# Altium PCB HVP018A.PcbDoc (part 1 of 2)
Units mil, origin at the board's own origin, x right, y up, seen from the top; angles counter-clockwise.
Board outline 2060 x 1591 mil, 4 copper layers (Top Layer, MidLayer1, MidLayer2, Bottom Layer), stack 46.2 mil thick; 91 components, 51 nets, 302 pads, 340 vias.
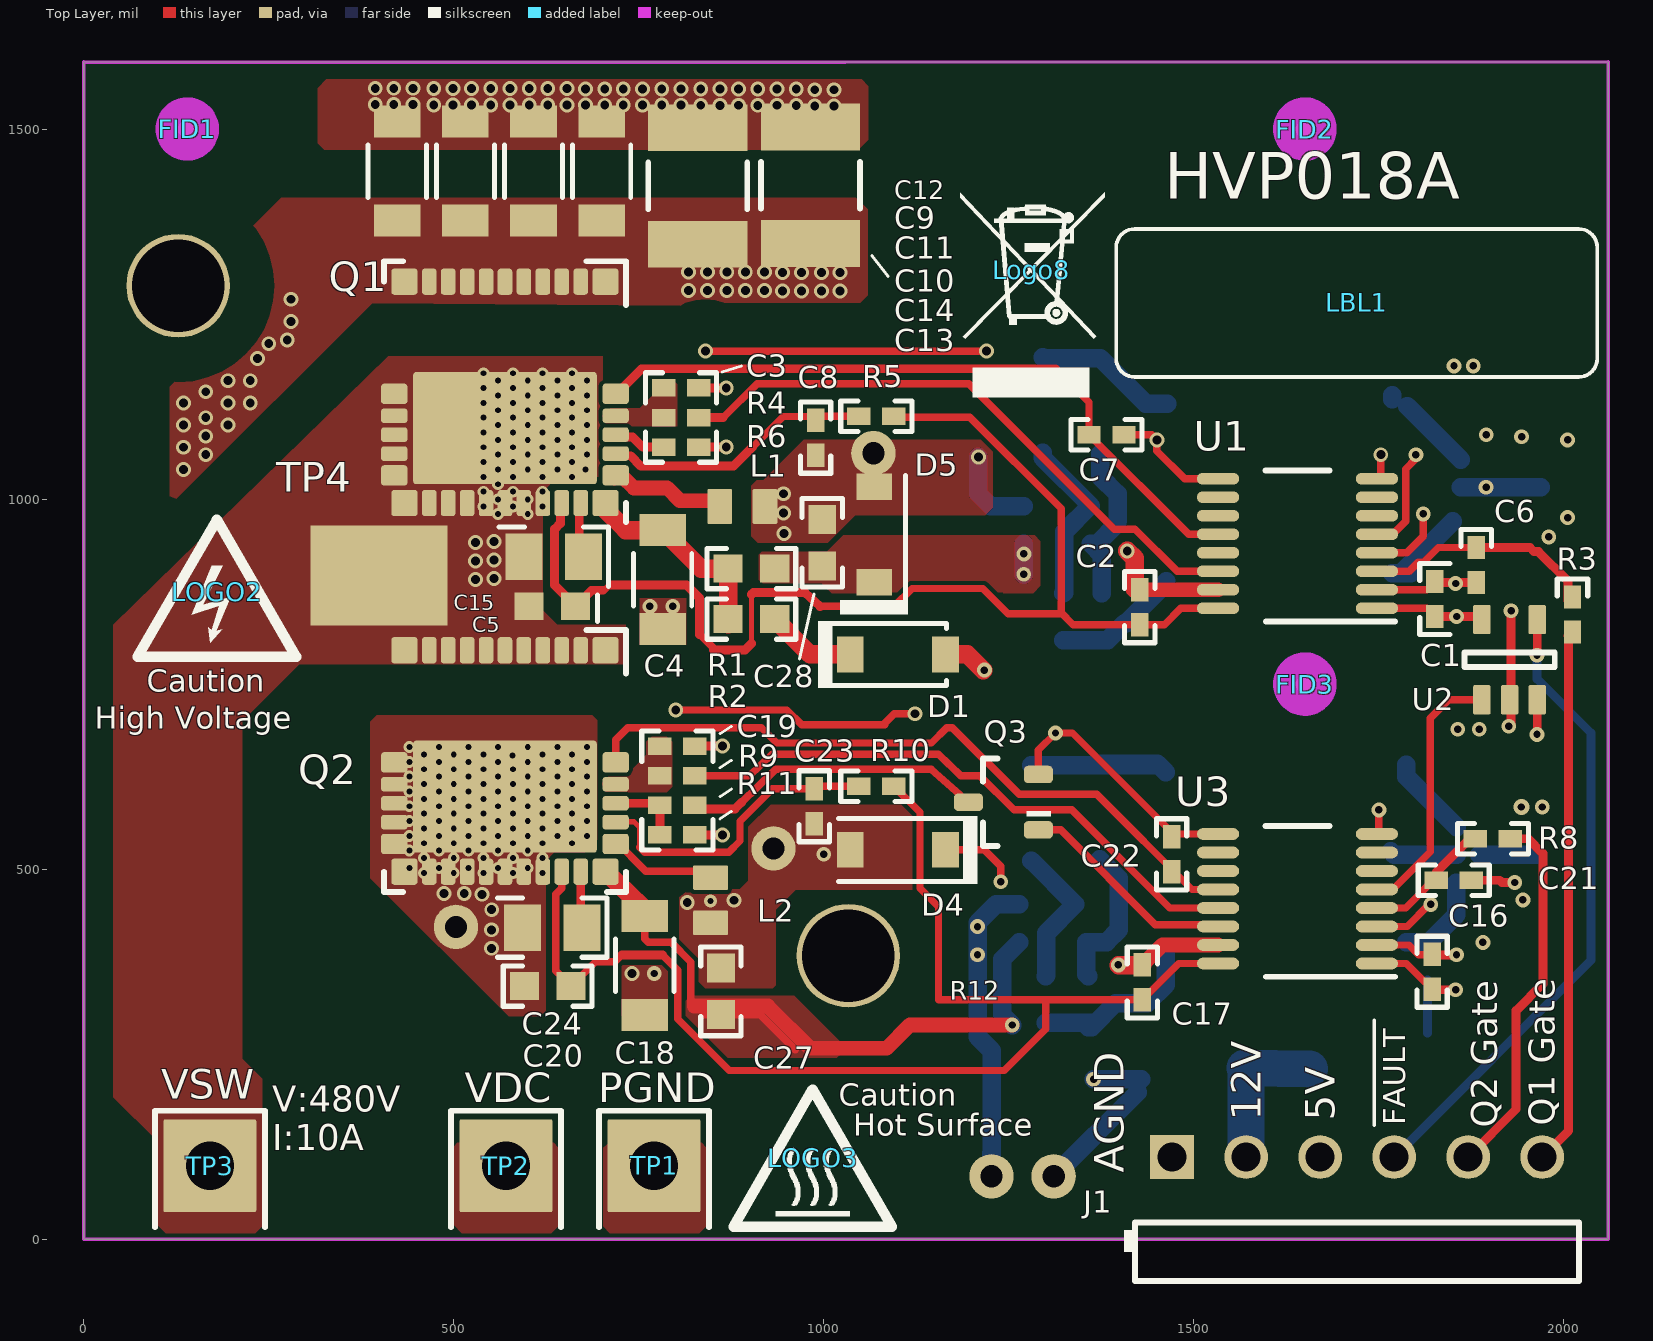
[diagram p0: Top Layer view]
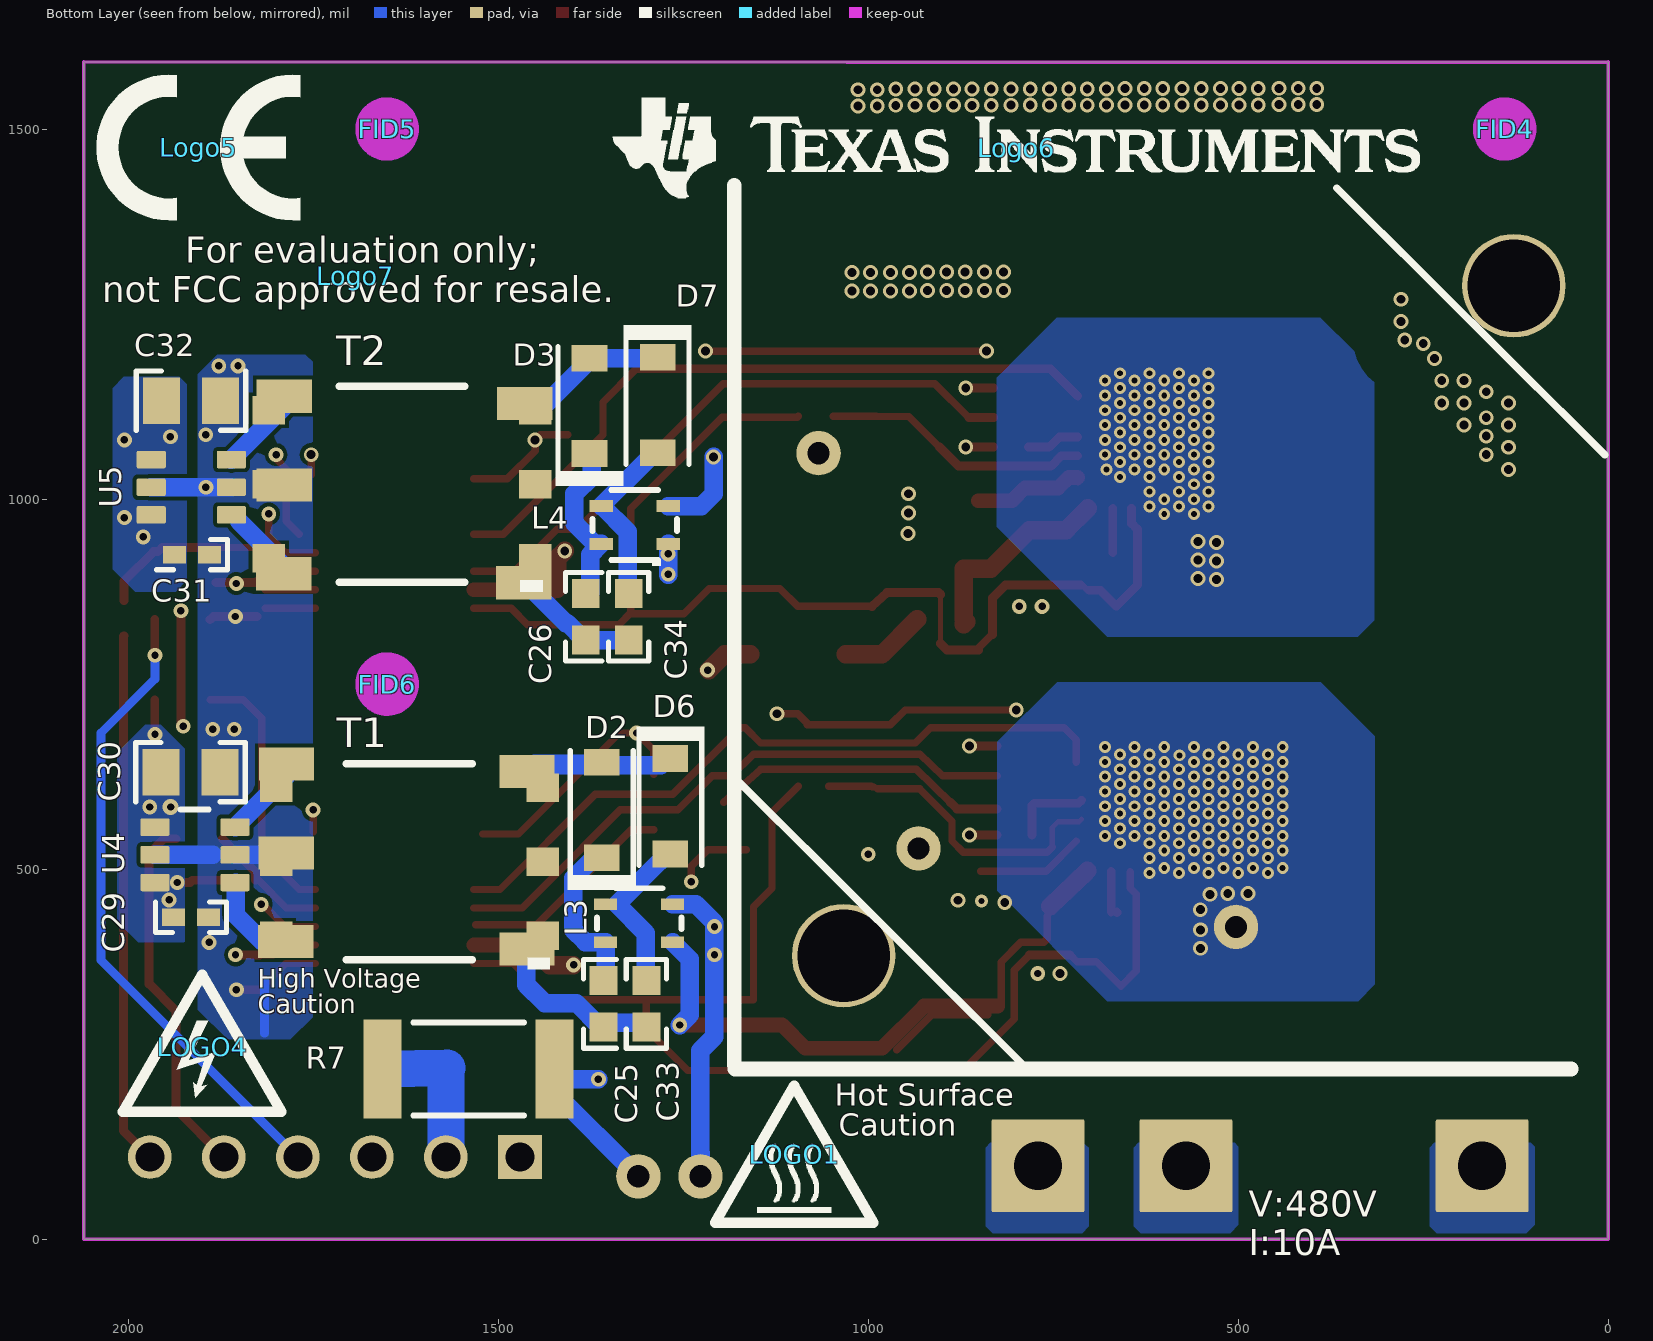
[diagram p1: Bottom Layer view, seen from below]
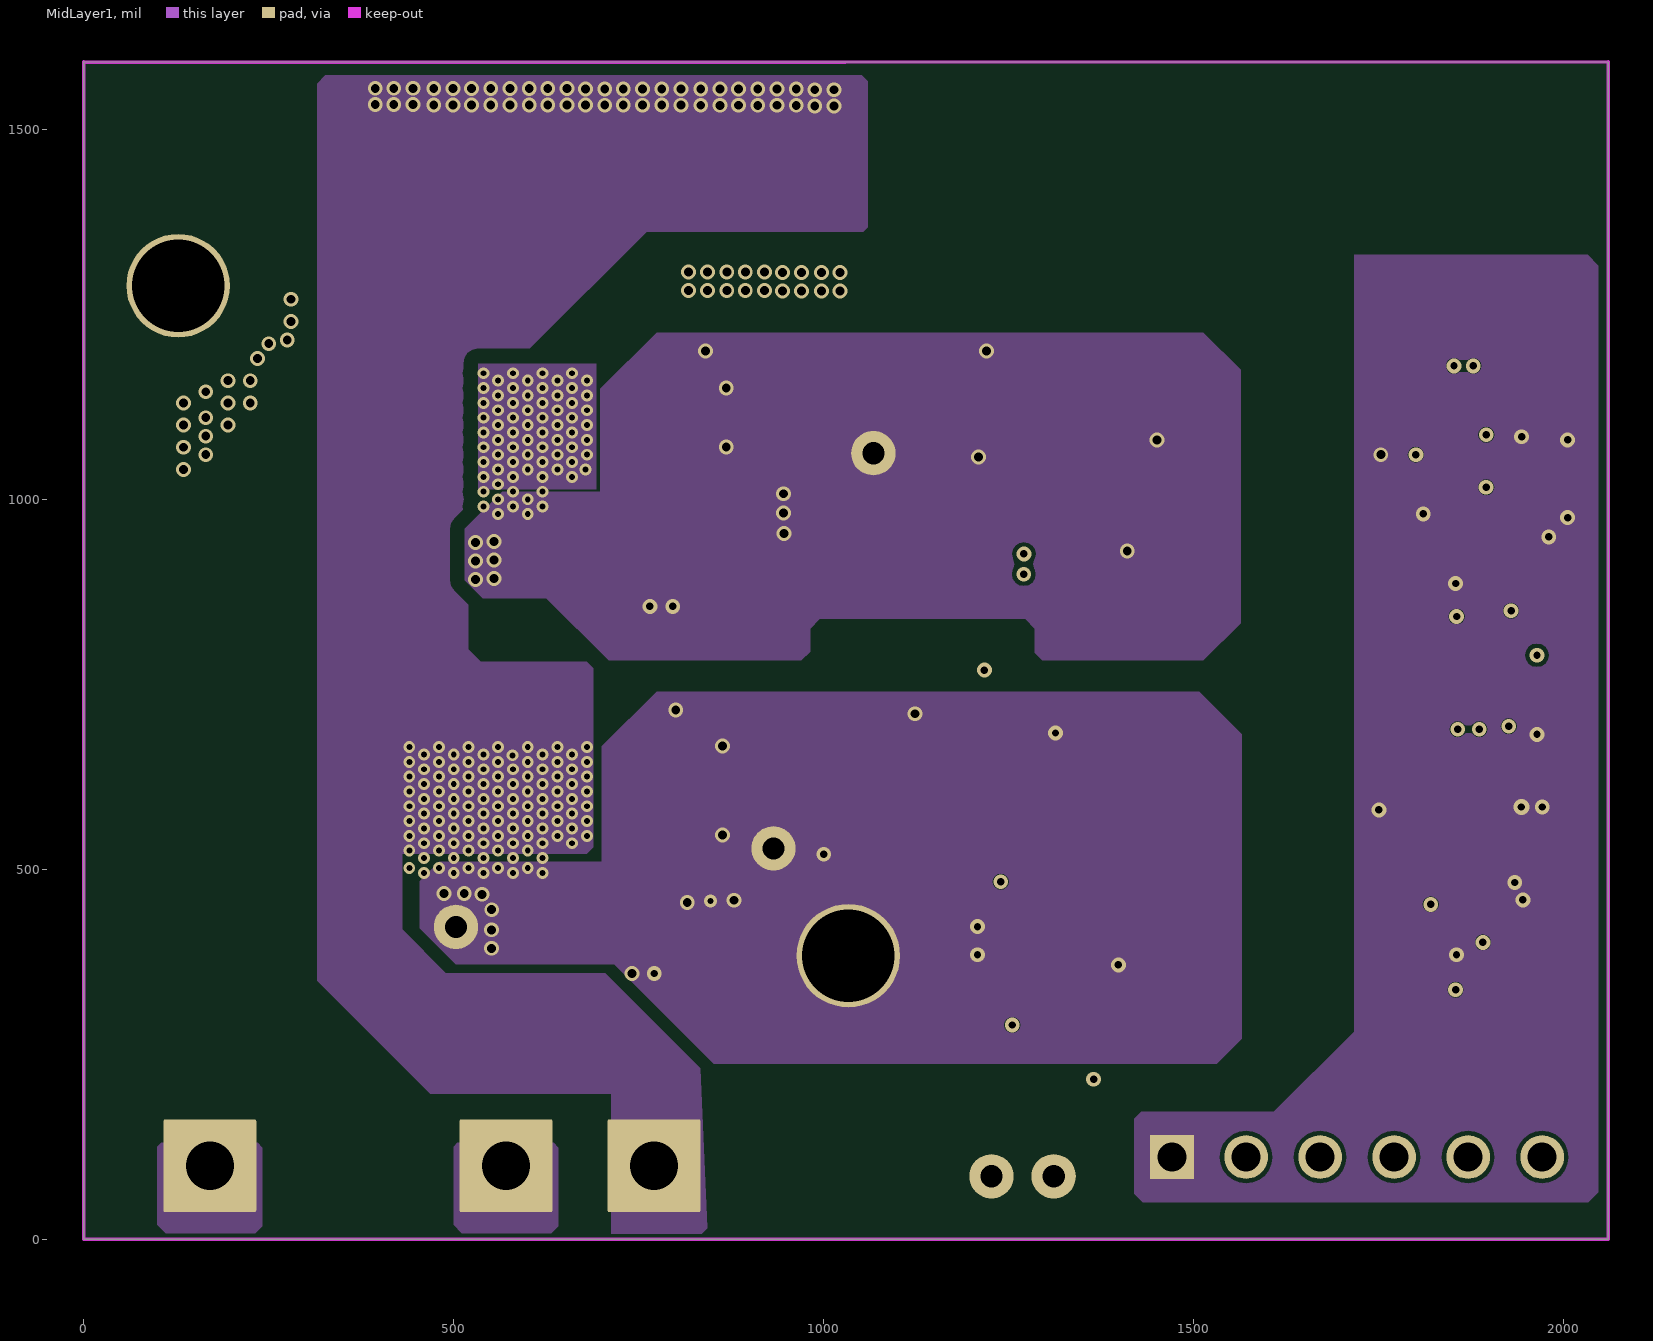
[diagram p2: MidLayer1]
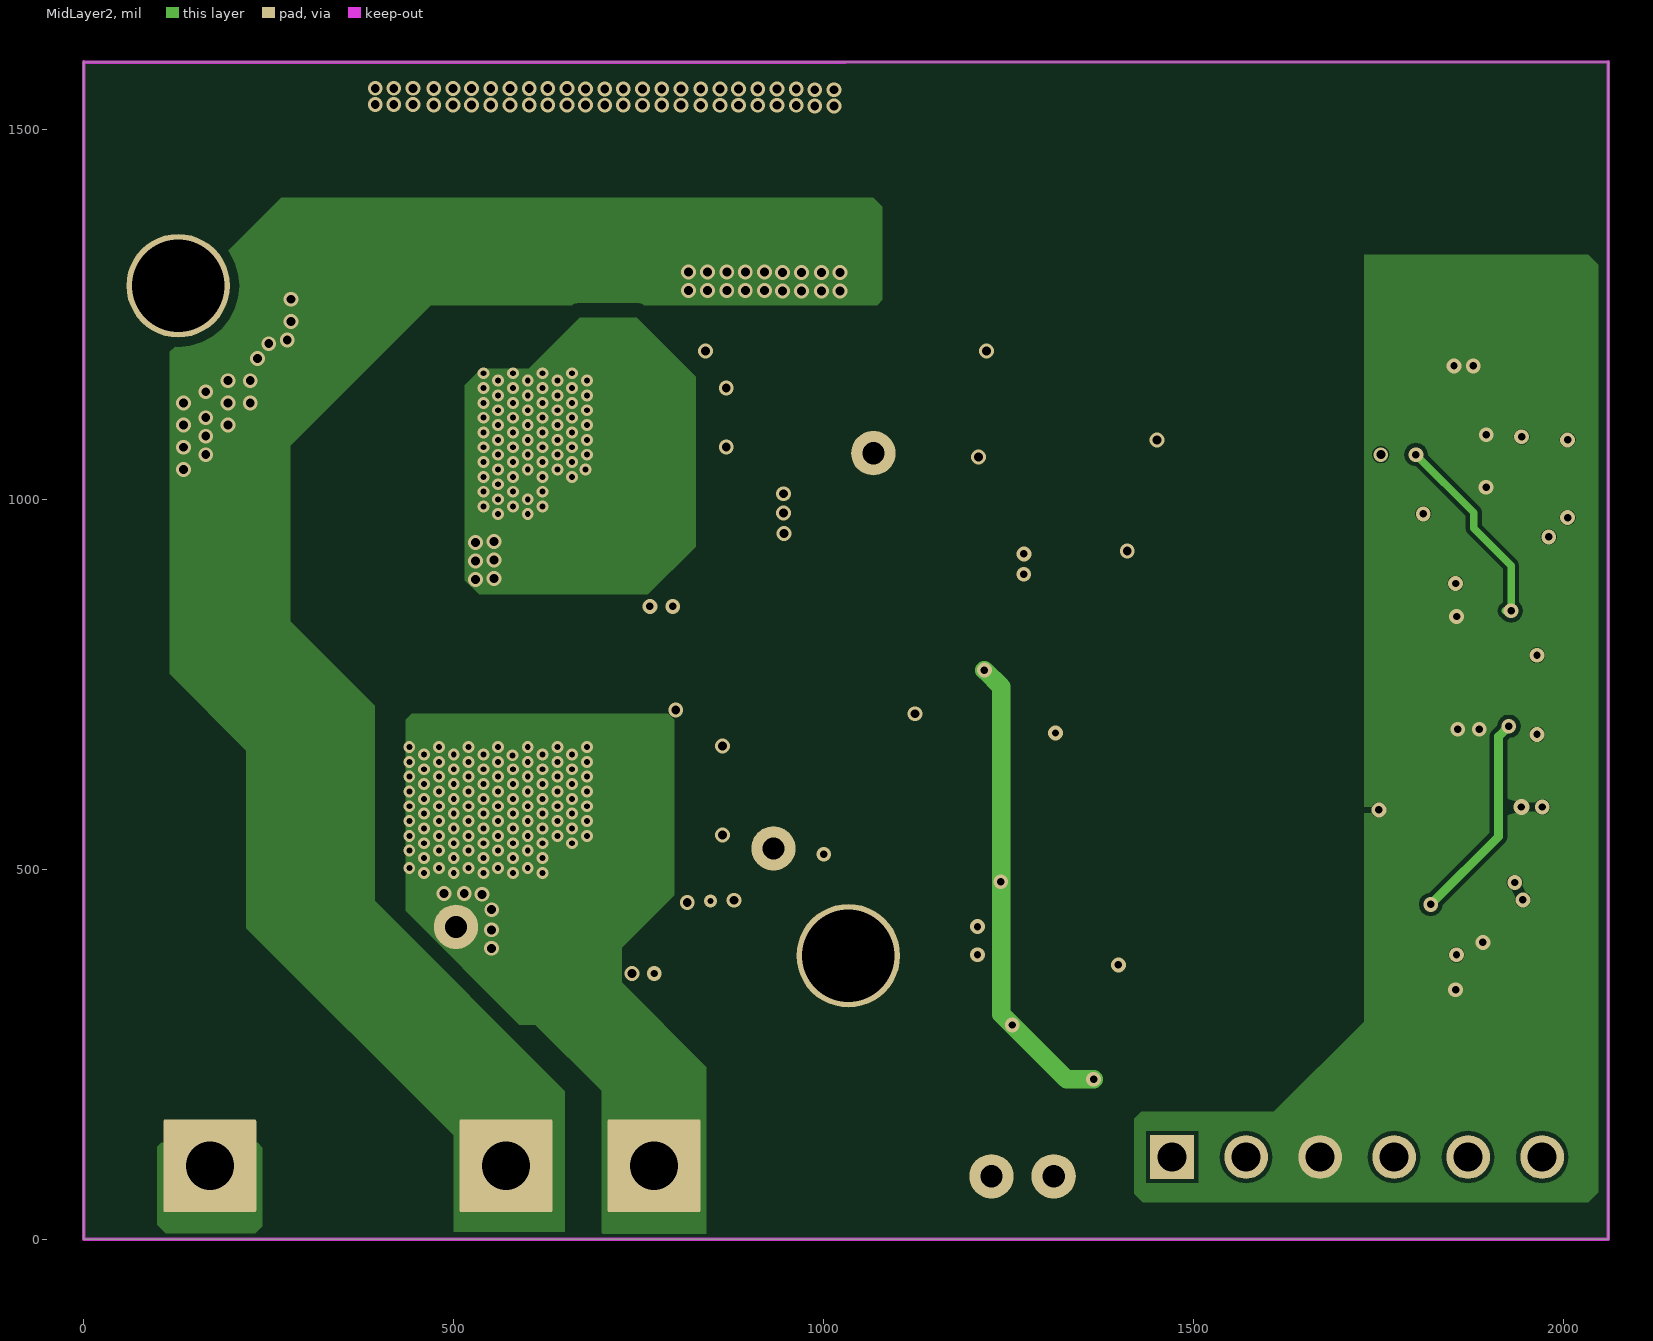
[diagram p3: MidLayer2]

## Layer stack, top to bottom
Top Solder: solder mask 0.4, Solder Resist, Dk 3.5
Top Layer: signal copper 2.8
Dielectric1: core 4.6, FR-4 High Tg, Dk 4.8
MidLayer1: signal copper 2.8
Dielectric2: prepreg 25.8, FR-4 High Tg, Dk 4.8
MidLayer2: signal copper 2.8
Dielectric3: core 4.6, FR-4 High Tg, Dk 4.8
Bottom Layer: signal copper 2.8
Bottom Solder: solder mask 0.4, Solder Resist, Dk 3.5

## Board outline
0,0 0,1591 2060,1590 2060,0

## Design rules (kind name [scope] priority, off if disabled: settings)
AcuteAngle [All] p1: minimum=4.50000000000000E+0001 checktracksonly=FALSE
AssemblyTestPointUsage [All] p1: valid=2
Clearance Clearance_HSPad_Mid2 [OnMid And InNetClass('HSPad') vs (OnMultiLayer Or OnMid) And Not InNetClass('HSPad')] p1: gap=20 ignorepadtopadclearanceinfootprint=FALSE except(0: Arc-Hole Track-Hole SMDPad-Hole THPad-Hole Via-Hole Fill-Hole Poly-Hole Region-Hole Text-Hole)
Clearance Clearance_HSPad_Mid1 [(OnMultiLayer Or OnMid) And InNetClass('HSPad') vs OnMid] p2: gap=20 ignorepadtopadclearanceinfootprint=FALSE except(0: Arc-Hole Track-Hole SMDPad-Hole THPad-Hole Via-Hole Fill-Hole Poly-Hole Region-Hole Text-Hole)
Clearance Clearance_HSPad [InNet('Heatsink_Pad')] p3: gap=45 ignorepadtopadclearanceinfootprint=FALSE
Clearance Clearance_HV_Connector [HasFootprint('Mill-Max_3620-1-32-15-00-00-08-0*') vs IsKeepOut] p4: gap=1 ignorepadtopadclearanceinfootprint=FALSE except(0: Arc-Hole Track-Hole SMDPad-Hole THPad-Hole Via-Hole Fill-Hole Poly-Hole Region-Hole Text-Hole)
Clearance Clearance_HV_Connector_1 [All vs IsKeepOut] p5: gap=5 ignorepadtopadclearanceinfootprint=FALSE except(0: Arc-Hole Track-Hole SMDPad-Hole THPad-Hole Via-Hole Fill-Hole Poly-Hole Region-Hole Text-Hole)
Clearance Clearance_BoardEdge_MountingHoles [OnCopper and InComponentClass('Mounting Holes') vs IsKeepOut] p6: gap=20 ignorepadtopadclearanceinfootprint=FALSE except(0: Arc-Hole Track-Hole SMDPad-Hole THPad-Hole Via-Hole Fill-Hole Poly-Hole Region-Hole Text-Hole)
Clearance Clearance_BoardEdge [OnCopper and Not InComponentClass('Logo') and not InComponentClass('FiducialMark') and not InRegion(1000,500,4000,800) and Not IsKeepout and Not OnMultiLayer vs IsKeepOut] p7: gap=15 ignorepadtopadclearanceinfootprint=FALSE except(0: Arc-Hole Track-Hole SMDPad-Hole THPad-Hole Via-Hole Fill-Hole Poly-Hole Region-Hole Text-Hole)
Clearance Clearance_HV2_Mid1 [OnMid And InNetClass('VSWNET') vs (OnMultiLayer Or OnMid) And Not InNetClass('VSWNET')] p8: gap=20 ignorepadtopadclearanceinfootprint=FALSE except(0: Arc-Hole Track-Hole SMDPad-Hole THPad-Hole Via-Hole Fill-Hole Poly-Hole Region-Hole Text-Hole)
Clearance Clearance_HV2_Mid2 [(OnMultiLayer Or OnMid) And InNetClass('VSWNET') vs OnMid And Not InNetClass('VSWNET')] p9: gap=20 ignorepadtopadclearanceinfootprint=FALSE except(0: Arc-Hole Track-Hole SMDPad-Hole THPad-Hole Via-Hole Fill-Hole Poly-Hole Region-Hole Text-Hole)
Clearance Clearance_HV2 [InNetClass('VSWNET') vs NOT InNetClass ('VSWNET')] p10: gap=60 ignorepadtopadclearanceinfootprint=FALSE except(0: Arc-Hole Track-Hole SMDPad-Hole THPad-Hole Via-Hole Fill-Hole Poly-Hole Region-Hole Text-Hole)
Clearance Clearance_HV1_Mid1 [(OnMultiLayer Or OnMid) And InNetClass('VHV') vs OnMid And Not InNetClass('VHV')] p11: gap=20 ignorepadtopadclearanceinfootprint=FALSE except(0: Arc-Hole Track-Hole SMDPad-Hole THPad-Hole Via-Hole Fill-Hole Poly-Hole Region-Hole Text-Hole)
Clearance Clearance_HV1_Mid2 [OnMid And InNetClass('VHV') vs (OnMultiLayer Or OnMid) And Not InNetClass('VHV')] p12: gap=20 ignorepadtopadclearanceinfootprint=FALSE except(0: Arc-Hole Track-Hole SMDPad-Hole THPad-Hole Via-Hole Fill-Hole Poly-Hole Region-Hole Text-Hole)
Clearance Clearance_HV1 [InNetClass('VHV') vs NOT InNetClass('VHV')] p13: gap=60 ignorepadtopadclearanceinfootprint=FALSE except(0: Arc-Hole Track-Hole SMDPad-Hole THPad-Hole Via-Hole Fill-Hole Poly-Hole Region-Hole Text-Hole)
Clearance [All] p14: gap=5.5 ignorepadtopadclearanceinfootprint=FALSE
ComponentClearance ComponentClearance_Shunt [InComponentClass('Header') vs InComponentClass('Shunt')] p1: gap=0 collisioncheckmode=3 verticalgap=0 showdistances=FALSE
ComponentClearance ComponentClearance_MountingHoles_FiducialMarks [InComponentClass('Mounting Holes') vs InComponentClass('FiducialMark')] p2: gap=50 collisioncheckmode=3 verticalgap=10 showdistances=FALSE
ComponentClearance ComponentClearance_Logo [InComponentClass('Logo')] p3: gap=0 collisioncheckmode=3 verticalgap=10 showdistances=FALSE
ComponentClearance ComponentClearance_ScrewToNut [(HasFootprint('NY PMS 440 0025 PH')) vs (HasFootprint('Keystone_1902C'))] p4: gap=5 collisioncheckmode=3 verticalgap=10 showdistances=FALSE
ComponentClearance ComponentClearance_MountingHoles [InComponentClass('Mounting Holes')] p5: gap=250 collisioncheckmode=3 verticalgap=100000 showdistances=FALSE
ComponentClearance ComponentClearance_SmallPassives [HasFootprint('0201*') or HasFootprint('0402*') or HasFootprint('0508') or HasFootprint('0603*') or HasFootprint('0612') or HasFootprint('0805*') or HasFootprint('0815*') or HasFootprint('0830*') or HasFootprint('1206*') or HasFootprint('1210*') or HasFootprint('1808*') or HasFootprint('1812*') or HasFootprint('1825*') or HasFootprint('2010*') or HasFootprint('2220*') or HasFootprint('2225*') or HasFootprint('2512*') or HasFootprint('2728*') or HasFootprint('3518*') vs HasFootprint('0201*') or HasFootprint('0402*') or HasFootprint('0508') or HasFootprint('0603*') or HasFootprint('0612') or HasFootprint('0805*') or HasFootprint('0815*') or HasFootprint('0830*') or HasFootprint('1206*') or HasFootprint('1210*') or HasFootprint('1808*') or HasFootprint('1812*') or HasFootprint('1825*') or HasFootprint('2010*') or HasFootprint('2220*') or HasFootprint('2225*') or HasFootprint('2512*') or HasFootprint('2728*') or HasFootprint('3518*')] p6: gap=15 collisioncheckmode=3 verticalgap=10 showdistances=FALSE
ComponentClearance ComponentClearance_THtoSMT [IsThruComponent vs IsSMTComponent] p7: gap=30 collisioncheckmode=3 verticalgap=30 showdistances=FALSE
ComponentClearance ComponentClearance_THtoTH [IsThruComponent vs IsThruComponent] p8: gap=74 collisioncheckmode=3 verticalgap=30 showdistances=FALSE
ComponentClearance [All] p9: gap=15 collisioncheckmode=3 verticalgap=10 showdistances=FALSE
DiffPairsRouting [All] p1: maxlimit=100 minlimit=10 mostfreqgap=10 toplayer_minwidth=15 toplayer_maxwidth=15 toplayer_prefwidth=15 midlayer1_minwidth=15 midlayer1_maxwidth=15 midlayer1_prefwidth=15 midlayer2_minwidth=15 midlayer2_maxwidth=15 midlayer2_prefwidth=15 bottomlayer_minwidth=15 bottomlayer_maxwidth=15 bottomlayer_prefwidth=15 maxuncoupledlength=1000
FabricationTestPointUsage TestPointUsage [All] p1: valid=2 allowmultiple=FALSE
FabricationTestpoint Testpoint [All] p1: side=3 testpointundercomponent=TRUE minsize=40 maxsize=100 preferedsize=60 minholesize=0 maxholesize=40 preferedholesize=32 testpointgrid=1 allowsidetop=TRUE allowsidebottom=TRUE usegrid=TRUE gridtolerance=0.01
FanoutControl Fanout_LCC [IsLCC] p1: bgadir=Out bgaviamode=Centered fanoutstyle=Auto fanoutdirection=Alternating viagrid=1 // Fanout_LCC (Default Rule)
FanoutControl Fanout_BGA [IsBGA] p2: bgadir=Out bgaviamode=Centered fanoutstyle=Auto fanoutdirection=Alternating viagrid=1 // Fanout_BGA (Default Rule)
FanoutControl Fanout_Default [All] p4: bgadir=Out bgaviamode=Centered fanoutstyle=Auto fanoutdirection=Alternating viagrid=1 // Fanout_Default (Default Rule)
FanoutControl Fanout_Small [(CompPinCount < 5)] p5: bgadir=Out bgaviamode=Centered fanoutstyle=Auto fanoutdirection=OutThenIn viagrid=1 // Fanout_Small (Default Rule)
HoleSize [All] p1: absolutevalues=TRUE maxlimit=251 minlimit=6 maxpercent=80.000 minpercent=20.000
MinimumAnnularRing MinimumAnnularRing_ThermalPadVias [IsVia and InAnyComponent] p1: minimumring=1
MinimumAnnularRing [IsVia] p2: minimumring=1
MinimumSolderMaskSliver MinimumSolderMaskSliver_Logo [InComponentClass('Logo') vs InComponentClass('Logo')] p1: minsoldermaskwidth=0.7
MinimumSolderMaskSliver [All] p2: minsoldermaskwidth=0
PlaneConnect [All] p1: planeconnectstyle=Relief reliefexpansion=10 reliefentries=4 reliefconductorwidth=10 reliefairgap=10
PolygonConnect [All] p1: connectstyle=Direct reliefconductorwidth=10 reliefentries=4 polygonreliefangle="90 Angle" airgapwidth=10
RoutingVias ThermalPadVias [IsVia and InAnyComponent] p1: holewidth=7.87 width=19.68 viastyle="Through Hole" minholewidth=7.87 minwidth=19.68 maxholewidth=12.99 maxwidth=23.62
RoutingVias [All] p2: holewidth=10 width=20 viastyle="Through Hole" minholewidth=6 minwidth=10 maxholewidth=40 maxwidth=65
SMDToCorner [All] p1: distance=30000
SilkToSilkClearance [All] p1: silktosilkclearance=0.01
SilkToSolderMaskClearance SilkscreenOverComponentPads [IsPad] p1: minsilkscreentomaskgap=0 clearancetoexposedcopper=TRUE
SolderMaskExpansion [All] p1: expansion=1.97
Width [All] p1: maxlimit=1000 minlimit=6 preferedwidth=10 checkconnectedcopper=TRUE
16 further rules are at their usual default settings.

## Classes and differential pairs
component class Label: LBL1
component class AssemblyNote: ZZ1 ZZ2 ZZ3 ZZ4
component class FiducialMark: FID1 FID2 FID3 FID4 FID5 FID6
component class HVP018A_Hardware: FID1 FID2 FID3 FID4 FID5 FID6 LBL1 LOGO1 LOGO2 LOGO3 LOGO4 Logo5 Logo6 Logo7 Logo8 ZZ1 ZZ2 ZZ3 ZZ4
component class Header: J1
net class VSWNET: 5V_H FAULT_H IN_H ISO_12V_H ISO_12V_H_B ISO_RET_H ISO_RET_H_B ISONC1 ISONC2 ISONC3 ISONC4 NetC4_1 NetC8_1 NetC26_2 NetD1_1 NetD3_2 NetQ1_30 NetR4_1 SW_H VM12V_H
net class VHV: HVBUS
component class HVP018A_DC: C1 C2 C3 C4 C5 C6 C7 C8 C9 C10 C11 C12 C13 C14 C15 C16 C17 C18 C19 C20 C21 C22 C23 C24 C25 C26 C27 C28 C29 C30 C31 C32 C33 C34 D1 D2 D3 D4 D5 D6 D7 J1 L1 L2 L3 L4 Q1 Q2 Q3 R1 R2 R3 R4 R5 R6 R7 R8 R9 R10 R11 R12 T1 T2 TP1 TP2 TP3 TP4 U1 U2 U3 U4 U5
component class Logo: Logo6

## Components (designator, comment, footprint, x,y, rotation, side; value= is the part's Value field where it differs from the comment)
C1 "C1005X5R1E105K050BC" 0402 1825.59,865 r90 top value=1uF
C2 "C1005X7R1H104K050BB" 0402 1427,854 r270 top value=0.1uF
C3 "C1005C0G1H220J050BA" 0402 807.24,1150.17 r180 top value=22pF
C4 "C1206C106K3RACTU" 1206_190 782.24,891.17 r270 top value=10uF
C5 "C1608X7R1H224K080AB" 0603 633.24,855.17 r180 top value=0.22uF
C6 "C1005C0G1H680J050BA" 0402 1881.59,911 r270 top value=68pF
C7 "C1005C0G1H680J050BA" 0402 1382,1087 r0 top value=68pF
C8 "C1005C0G1H680J050BA" 0402 989,1083 r270 top value=68pF
C9 "C1206C223KDRACTU" 1206_190 515.78,1443.17 r90 top value=0.022uF
C10 "C1206C223KDRACTU" 1206_190 699.78,1443.17 r90 top value=0.022uF
C11 "C1206C223KDRACTU" 1206_190 607.78,1443.17 r90 top value=0.022uF
C12 "C1206C223KDRACTU" 1206_190 423.78,1443.17 r90 top value=0.022uF
C13 "C1812W104KDRACTU" 1812_254 982,1424 r90 top value=0.1uF
C14 "C1812W104KDRACTU" 1812_254 829.68,1423.17 r90 top value=0.1uF
C15 "GRM219R61E225KA12D" 0805_HV 635.24,922.17 r180 top value=2.2uF
C16 "C1005X5R1E105K050BC" 0402 1821.81,361.38 r90 top value=1uF
C17 "C1005X7R1H104K050BB" 0402 1430.59,347 r270 top value=0.1uF
C18 "C1206C106K3RACTU" 1206_190 758,370 r270 top value=10uF
C19 "C1005C0G1H220J050BA" 0402 802.14,666.24 r180 top value=22pF
C20 "C1608X7R1H224K080AB" 0603 627,342 r180 top value=0.22uF
C21 "C1005C0G1H680J050BA" 0402 1851.21,485 r0 top value=68pF
C22 "C1005C0G1H680J050BA" 0402 1470,520 r90 top value=68pF
C23 "C1005C0G1H680J050BA" 0402 987,585 r270 top value=68pF
C24 "GRM219R61E225KA12D" 0805_HV 633.11,421 r180 top value=2.2uF
C25 "C1608X5R1V475K080AC" 0603 1357.59,318 r270 bottom value=4.7uF
C26 "C1608X5R1V475K080AC" 0603 1381.59,841 r270 bottom value=4.7uF
C27 "C1608X5R1V475K080AC" 0603 861,335 r90 top value=4.7uF
C28 "C1608X5R1V475K080AC" 0603 998,941 r90 top value=4.7uF
C29 "C1005X7R1H104K050BB" 0402 1915,435 r0 bottom value=0.1uF
C30 "GCM21BR71C475KA73L" 0805_HV 1915.59,631 r0 bottom value=4.7uF
C31 "C1005X7R1H104K050BB" 0402 1913.6,925 r0 bottom value=0.1uF
C32 "GCM21BR71C475KA73L" 0805_HV 1915,1133 r0 bottom value=4.7uF
C33 "C1608X5R1V475K080AC" 0603 1299.59,318 r90 bottom value=4.7uF
C34 "C1608X5R1V475K080AC" 0603 1323.59,841 r90 bottom value=4.7uF
D1 "UFM15PL-TP" SOD-123FL 1100,790 r0 top value=600V
D2 "B0530W-7-F" SOD-123 1360,580 r90 bottom value=30V
D3 "B0530W-7-F" SOD-123 1376.59,1126 r90 bottom value=30V
D4 "BZT52C16-7-F" SOD-123 1100,526 r180 top value=16V
D5 "BZT52C16-7-F" SOD-123 1068,952 r90 top value=16V
D6 "B0530W-7-F" SOD-123 1267.29,585 r270 bottom value=30V
D7 "B0530W-7-F" SOD-123 1284.59,1127 r270 bottom value=30V
FID1 "Fiducial" Fiducial6.4-20 140,1500 r0 top
FID2 "Fiducial" Fiducial6.4-20 1650,1500 r0 top
FID3 "Fiducial" Fiducial6.4-20 1650,750 r0 top
FID4 "Fiducial" Fiducial6.4-20 140,1500 r180 bottom
FID5 "Fiducial" Fiducial6.4-20 1650,1500 r180 bottom
FID6 "Fiducial" Fiducial6.4-20 1650,750 r180 bottom
J1 "90121-0766" Molex_90121-0766 1720.59,111 r0 top
L1 "74404020100" WE-LQS_2010 890,990 r180 top value=10uH
L2 "74404020100" WE-LQS_2010 847,458 r90 top value=10uH
L3 "ACM2520-601-2P-T002" TDK_ACM2520-2P 1309.59,427 r0 bottom
L4 "ACM2520-601-2P-T002" TDK_ACM2520-2P 1315.59,965 r0 bottom
LBL1 "THT-14-423-10" Label_650x200 1720,1265 r180 top
LOGO1 "CAUTION HOT SURFACE" IEC_HotSurface_Small 1100,115 r180 bottom
LOGO2 "DANGER HIGH VOLTAGE" IEC_HighVoltage_Small 180,875 r0 top
LOGO3 "CAUTION HOT SURFACE" IEC_HotSurface_Small 985,110 r0 top
LOGO4 "DANGER HIGH VOLTAGE" IEC_HighVoltage_Small 1900,260 r180 bottom
Logo5 "CE Mark" CE_Mark_5mm 1905,1475 r180 bottom
Logo6 "Texas Instruments" TI_Horizontal_Overlay_Small 800,1475 r180 bottom
Logo7 "FCC disclaimer" FCC_disclaimer_stacked 1693,1301 r180 bottom
Logo8 "WEEE logo" WEEE_Minimum 1280,1310 r0 top
Q1 "LMG3410R050RWHT" RWH0032A_NV 569.24,1144.17 r270 top
Q2 "LMG3410R050RWHT" RWH0032A_NV 569.24,646.17 r270 top
Q3 "MGSF1N02LT1G" SOT-23 1242.69,590.5 r180 top value=20V
R1 "MCT06030Z0000ZP500" 0603 902.24,906.17 r180 top value=0
R2 "CRCW060320R0JNEA" 0603 902.24,837.92 r180 top value=20
R3 "RC0402FR-0749R9L" 0402 2011.59,844 r90 top value=49.9
R4 "RC0402FR-0749R9L" 0402 807.24,1110.17 r180 top value=49.9
R5 "ERJ-2RKF1002X" 0402 1071,1112 r180 top value=10.0k
R6 "CRCW040215K0JNED" 0402 807.24,1070.17 r180 top value=15k
R7 "CRCW25120000Z0EG" 2512 1540,230 r180 bottom value=0
R8 "RC0402FR-0749R9L" 0402 1904.01,541 r180 top value=49.9
R9 "RC0402FR-0749R9L" 0402 802.14,626.24 r180 top value=49.9
R10 "ERJ-2RKF1002X" 0402 1071,612 r180 top value=10.0k
R11 "CRCW040217K8FKED" 0402 802.14,586.24 r180 top value=17.8k
R12 "RC1005F104CS" 0402 802.14,546.24 r180 top value=100k
T1 "760390014" Wurth_760390013 1620,510 r0 bottom value=475uH
T2 "760390014" Wurth_760390013 1630,1020 r0 bottom value=475uH
TP1 "3620-2-32-15-00-00-08-0" Mill-Max_3620-2-32-xx-00-00-08-0 770.59,0 r0 top
TP2 "3620-2-32-15-00-00-08-0" Mill-Max_3620-2-32-xx-00-00-08-0 570.59,0 r0 top
TP3 "3620-2-32-15-00-00-08-0" Mill-Max_3620-2-32-xx-00-00-08-0 170.59,0 r0 top
TP4 "5016" Testpoint_Keystone_Compact 399,897 r180 top
U1 "ISO7731DBQR" DBQ0016A_N 1640,940 r180 top
U2 "SN74AHC1G08DBVR" DBV0005A_N 1926.59,783 r90 top
U3 "ISO7731DBQR" DBQ0016A_N 1640,460 r180 top
U4 "SN6505BDBVR" DBV0006A_N 1909.59,519.35 r0 bottom
U5 "SN6505BDBVR" DBV0006A_N 1914.59,1016 r0 bottom
ZZ1 "These assemblies are ESD sensitive, ESD precautions shall be observed." AssemblyNote 10,2251.72 r0 top
ZZ2 "These assemblies must be clean and free from flux and all contaminants. Use of no clean flux is not acceptable." AssemblyNote 10,2161.72 r0 top
ZZ3 "These assemblies must comply with workmanship standards IPC-A-610 Class 2, unless otherwise specified." AssemblyNote 10,2046.72 r0 top
ZZ4 "Install label in silkscreened box after final wash. Text shall be 8 pt font. Text shall be per the label table in the PDF schematic" AssemblyNote 10.59,1927.49 r0 top

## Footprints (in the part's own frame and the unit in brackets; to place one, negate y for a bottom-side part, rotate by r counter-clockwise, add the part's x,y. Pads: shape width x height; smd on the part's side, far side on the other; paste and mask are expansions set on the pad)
0402 [mm] "0402 from SM-752 data"
  rect 0.8x0.6 smd: 1(-0.6,0) 2(0.6,0)
  silkscreen extent -1.22,-0.52 1.22,0.52, body extent -0.55,-0.3 0.55,0.3, height 0.6
0603 [mm] "0603 from SM-752 data"
  rect 1x0.95 smd: 1(-0.8,0) 2(0.8,0)
  silkscreen extent -1.55,-0.38 -1.55,0.51, body extent -0.87,-0.47 0.87,0.47, height 1
0805_HV [mil] "0805 with 30mil clearance between pads"
  rect 50x63 smd: 1(-40,0) 2(40,0)
  silkscreen extent -74,-40 74,40, body extent -43,-29 43,29, height 57
1206_190 [mm] "1206_190"
  rect 1.1x1.6 smd: 1(-1.7,0) 2(1.7,0)
  silkscreen extent -0.9,-1 0.9,1, body extent -1.75,-0.95 1.75,0.95, height 1.9
1812_254 [mm] "SMD, 2-Leads, Body 4.8x3.4mm"
  rect 1.6x3.4 smd: 1(-2,0) 2(2,0)
  silkscreen extent -0.8,-1.7 0.8,1.7, body extent -2.4,-1.7 2.4,1.7, height 2.54
2512 [mm] "Chip Resistor, Body 6.3x3.2mm, IPC Medium Density"
  rect 1.3x3.4 smd: 1(-2.95,0) 2(2.95,0)
  silkscreen extent -1.9,-1.6 1.9,1.6, body extent -3.22,-1.67 3.22,1.67, height 0.71
AssemblyNote [mil] "Assembly Note"
CE_Mark_5mm [mil] "Minimum text height for CE Mark"
  silkscreen extent -138,-98 138,98
DBQ0016A_N [mm] "SOP, 16-Leads, Body 4.9x3.9mm, Pitch 0.635mm, IPC Medium Density"
  oval 1.45x0.4 smd: 1(-2.725,2.222) 2(-2.725,1.587) 3(-2.725,0.952) 4(-2.725,0.317) 5(-2.725,-0.318) 6(-2.725,-0.953) 7(-2.725,-1.588) 8(-2.725,-2.223) 9(2.725,-2.222) 10(2.725,-1.587) 11(2.725,-0.952) 12(2.725,-0.317) 13(2.725,0.318) 14(2.725,0.953) 15(2.725,1.588) 16(2.725,2.223)
  silkscreen extent -3.35,-2.5 1.1,2.67, body extent -3.01,-2.45 3.01,2.45, height 1.63
DBV0005A_N [mm] "SOT23, 5-Leads, Body 2.9x1.6mm, Pitch 0.95mm, Lead Span 2.8mm, IPC Medium Density"
  rrect17% 1x0.6 smd: 1(-1.375,0.95) 2(-1.375,0) 3(-1.375,-0.95) 4(1.375,-0.95) 5(1.375,0.95)
  silkscreen extent -0.25,-1.55 0.25,1.55, body extent -1.42,-1.46 1.42,1.46, height 1.09
DBV0006A_N [mm] "SOT23, 6-Leads, Body 2.9x1.6mm, Pitch 0.95mm, Lead Span 2.8mm, IPC Medium Density"
  rrect17% 1x0.6 smd: 1(-1.375,0.95) 2(-1.375,0) 3(-1.375,-0.95) 4(1.375,-0.95) 5(1.375,0) 6(1.375,0.95)
  silkscreen extent -0.47,-1.55 0.5,-1.55, body extent -1.42,-1.46 1.42,1.46, height 1.12
FCC_disclaimer_stacked [mil]
Fiducial6.4-20 [mil]
  round 25 smd mask+26.87: 1(0,0)
  Top Layer keep-out circle w46.37: c0,0 r19.68
IEC_HighVoltage_Small [mil]
  silkscreen extent -107,-88 107,97
IEC_HotSurface_Small [mil]
  silkscreen extent -107,-93 107,92
Label_650x200 [mil] "Thermal Transfer Label"
  round 1 on Mech13: 0(0,0)
  silkscreen extent -325,-100 325,100, body extent -325,-100 325,100, height 1
Mill-Max_3620-2-32-xx-00-00-08-0 [mm] "PCB Pin, 0.04\" DIA, R/A, Edge-Mount"
  rrect3% 3.18x3.18 hole 1.65: 1(0,2.52)
  silkscreen extent -1.89,0.41 1.89,4.41, body extent -1.59,-5.06 1.59,4.11, height 0.65
Molex_90121-0766 [mm] "Header, 2.54mm, 6x1, R/A, TH"
  rect 1.5x1.5 hole 1: 1(-6.35,0)
  round 1.5 hole 1: 2(-3.81,0) 3(-1.27,0) 4(1.27,0) 5(3.81,0) 6(6.35,0)
  silkscreen extent -8,-4.25 7.62,-2.25, body extent -7.62,-11 7.62,0.32, height 3.63
RWH0032A_NV [mm] "VQFN, 32-Lead, Body 8x8mm"
  rrect22% 0.9x0.9 smd paste-0.07 mask-0.05: 1(-3.8,3.45) 11(-3.8,-3.45) 17(3.8,-3.45) 27(3.8,3.45)
  rrect40% 0.9x0.5 smd paste-0.05 mask-0.05: 2(-3.8,2.6) 3(-3.8,1.95) 4(-3.8,1.3) 5(-3.8,0.65) 6(-3.8,0) 7(-3.8,-0.65) 8(-3.8,-1.3) 9(-3.8,-1.95) 10(-3.8,-2.6) 18(3.8,-2.6) 19(3.8,-1.95) 20(3.8,-1.3) 21(3.8,-0.65) 22(3.8,0) 23(3.8,0.65) 24(3.8,1.3) 25(3.8,1.95) 26(3.8,2.6)
  rrect29% 0.7x0.9 smd paste-0.05 mask-0.05: 12(0.05,-3.8) 16(2.85,-3.8) 28(2.85,3.8) 32(0.05,3.8)
  rrect40% 0.5x0.9 smd paste-0.05 mask-0.05: 13(0.8,-3.8) 14(1.45,-3.8) 15(2.1,-3.8) 29(2.1,3.8) 30(1.45,3.8) 31(0.8,3.8)
  rrect10% 1.6x0.99 on Top Paste: 33(0.314,2.38) 33(0.314,1.19) 33(0.314,0) 33(0.314,-1.19) 33(0.314,-2.38) 33(2.114,1.19) 33(2.114,2.38) 33(2.114,0) 33(2.114,-2.38) 33(2.114,-1.19)
  rrect5% 3.85x6.3 smd paste-2 mask-0.05: 33(1.225,0)
  silkscreen extent -4.5,-4.15 4.45,4.15, body extent -4,-4 4,4, height 0.9
SOD-123 [mm] "On Semi recommended land pattern"
  rect 0.915x1.22 smd: 1(-1.637,0) 2(1.637,0)
  silkscreen extent -2.74,-1.17 2.03,1.17, body extent -1.93,-0.9 1.93,0.9, height 1.35
SOD-123FL [mm] "Copied from SOD-123"
  rect 0.915x1.22 smd: 1(-1.637,0) 2(1.637,0)
  silkscreen extent -2.74,-1.16 1.68,1.16, body extent -1.9,-0.9 1.9,0.9, height 1
SOT-23 [mm] "SOT23, 3-Leads, Body 2.9x1.3mm, Pitch 0.95mm, Lead Span 2.5mm, IPC Medium Density"
  rrect50% 1x0.6 smd: 1(-1.2,0.95) 2(-1.2,-0.95) 3(1.2,0)
  silkscreen extent -1.62,-1.5 0.7,1.5, body extent -1.16,-1.45 1.21,1.45, height 1
TDK_ACM2520-2P [mm] "SMD, 4-Leads, Body 2.5x2mm"
  rect 0.8x0.4 smd: 1(-1.15,0.65) 2(-1.15,-0.65) 3(1.15,-0.65) 4(1.15,0.65)
  silkscreen extent -1.45,-1.2 1.45,0.2, body extent -1.35,-1.1 1.35,1.1, height 1.3
Testpoint_Keystone_Compact [mil] "Compact SMT test point"
  rect 185x135 smd: 1(0,0)
  body extent -75,-56 75,56, height 91
TI_Horizontal_Overlay_Small [mil]
  silkscreen extent -545,-68 545,67
WE-LQS_2010 [mm] "SMD, 2-Leads, Body 2x1.6mm"
  rrect12% 0.85x1.2 smd: 1(-0.775,0) 2(0.775,0)
  body extent -1,-0.82 1,0.8, height 0.98
WEEE_Minimum [mil] "WEEElie bin"
  silkscreen extent -95,-172 99,104
Wurth_760390013 [mil] "Wurth"
  rect 44x38 smd: 1(-180,100) 2(-180,0) 3(-180,-100) 4(180,-100) 5(180,0) 6(180,100)
  silkscreen extent -190,-132 85,145, body extent -198,-135 198,130, height 166

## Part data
C1 C16: library part CMP-0006276-2, "CAP, CERM, 1 uF, 25 V, +/- 10%, X5R, 0402", Alternate Manufacturer=TDK, Alternate PartNumber=C1005X5R1E225K050BC, Cap_Case=0402, Supplier Part Number 1=445-9066-1-ND, TempCo=X5R, Tolerance_%=10%, Value1=Unknown, Value2=25V, ValueDisplayed=1uF
C2 C17 C29 C31: library part CMP-0006297-2, "CAP, CERM, 0.1 uF, 50 V, +/- 10%, X7R, 0402", Alternate Manufacturer="Wurth Elektronik", Alternate PartNumber=885012205037, Cap_Case=0402, Manufacturer=TDK, Supplier Part Number 1=445-5932-1-ND, TempCo=X7R, Tolerance_%=10%, Value1="0.039064 ohm", Value2=50V, ValueDisplayed=0.1uF
C3 C19: library part CMP-0006248-2, "CAP, CERM, 22 pF, 50 V, +/- 5%, C0G/NP0, 0402", Alternate Manufacturer=TDK, Alternate PartNumber=CGA2B2NP01H220J050BA, Cap_Case=0402, Supplier Part Number 1=445-1239-1-ND, TempCo=C0G/NP0, Tolerance_%=5%, Value1=Unknown, Value2=50V, ValueDisplayed=22pF
C4 C18: library part CMP-0008589-2, "CAP, CERM, 10 uF, 25 V, +/- 10%, X7R, 1206_190", Cap_Case=1206, Manufacturer=Kemet, Supplier Part Number 1=399-7442-1-ND, TempCo=X7R, Tolerance_%=10%, Value1=Unknown, Value2=25V, ValueDisplayed=10uF
C5 C20: library part CMP-0007047-4, "CAP, CERM, 0.22 uF, 50 V, +/- 10%, X7R, 0603", Alternate Manufacturer=Kemet, Alternate PartNumber=C0603C224J3RAC7867, Cap_Case=0603, Manufacturer=TDK, Supplier Part Number 1=445-7408-1-ND, TempCo=X7R, Tolerance_%=10%, Value1="0.021699 ohm", Value2=50V, ValueDisplayed=0.22uF
C6 C7 C8 C21 C22 C23: library part CMP-0006251-2, "CAP, CERM, 68 pF, 50 V, +/- 5%, C0G/NP0, 0402", Alternate Manufacturer=Murata, Alternate PartNumber=GRM1555C1H680JA01D, Cap_Case=0402, Manufacturer=TDK, Supplier Part Number 1=445-1245-1-ND, TempCo=C0G/NP0, Tolerance_%=5%, Value1=Unknown, Value2=50V, ValueDisplayed=68pF
C9 C10 C11 C12: library part CMP-0084048-1, "CAP, CERM, 0.022 µF, 1000 V,+/- 10%, X7R, AEC-Q200 Grade 1, 1206", Cap_Case=1206, Manufacturer=Kemet, TempCo=X7R, Tolerance_%=10%, Value2=1000V, ValueDisplayed=0.022µF
C13 C14: library part CMP-0009326-2, "CAP, CERM, 0.1 uF, 1000 V, +/- 10%, X7R, 1812", Cap_Case=1812, Manufacturer=Kemet, Supplier Part Number 1=399-6523-1-ND, TempCo=X7R, Tolerance_%=10%, Value1=Unknown, Value2=1000V, ValueDisplayed=0.1uF
C15 C24: library part CMP-0008208-1, "CAP, CERM, 2.2 uF, 25 V, +/- 10%, X5R, 0805", Cap_Case=0805, Manufacturer=MuRata, Supplier Part Number 1=490-1701-1-ND, TempCo=X5R, Tolerance_%=10%, Value1="0.006 ohm", Value2=25V, ValueDisplayed=2.2uF
C25 C26 C27 C28 C33 C34: library part CMP-0007022-5, "CAP, CERM, 4.7 uF, 35 V, +/- 10%, X5R, 0603", Cap_Case=0603, Manufacturer=TDK, Supplier Part Number 1=445-9064-1-ND, TempCo=X5R, Tolerance_%=10%, Value1="0.003728 ohm", Value2=35V, ValueDisplayed=4.7uF
C30 C32: library part CMP-0008020-2, "CAP, CERM, 4.7 uF, 16 V, +/- 10%, X7R, AEC-Q200 Grade 1, 0805", Cap_Case=0805, Manufacturer=MuRata, Supplier Part Number 1=490-5332-1-ND, TempCo=X7R, Tolerance_%=10%, Value1=Unknown, Value2=16V, ValueDisplayed=4.7uF
D1: library part CMP-0029148-1, "Diode, Ultrafast, 600 V, 1 A, SOD-123FL", Manufacturer="Micro Commercial Components", Supplier Part Number 1=UFM15PL-TPMSCT-ND, Value1=1A, Value2=1.7V
D2 D3 D6 D7: library part CMP-0028643-1, "Diode, Schottky, 30 V, 0.5 A, SOD-123", Manufacturer="Diodes Inc.", Supplier Part Number 1=B0530W-FDICT-ND, Value1=0.5A, Value2=0.43V
D4 D5: library part CMP-0005769-2, "Diode, Zener, 16 V, 500 mW, AEC-Q101, SOD-123", Manufacturer="Diodes Inc.", Power_W=500mW, Supplier Part Number 1=BZT52C16-FDICT-ND, Value1=0.5W
FID1 FID2 FID3 FID4 FID5 FID6: library part CMP-0077181-1, "Fiducial mark.  There is nothing to buy or mount.", Manufacturer=N/A
J1: library part CMP-0055334-1, "Header, 2.54mm, 6x1, Gold, R/A, TH", Color=Black, Current_A=3A, Manufacturer=Molex, Supplier Part Number 1=WM8112-ND, Voltage_V=350V
L1 L2: library part CMP-0063789-1, "Inductor, 10 uH, 0.5 A, 0.85 ohm, SMD", Manufacturer="Wurth Elektronik", Value1="0.85 ohm", Value2=0.5A, ValueDisplayed=10uH
L3 L4: library part CMP-0013161-2, "Coupled inductor, 0.2 A, 0.45 ohm, SMD", Manufacturer=TDK, Supplier Part Number 1=445-8930-1-ND
LBL1: library part CMP-0003625-1, "Thermal Transfer Printable Labels, 0.650\" W x 0.200\" H - 10,000 per roll", Manufacturer=Brady, Supplier Part Number 1=97C5133
LOGO1 LOGO3: library part CMP-0074837-1, "IEC 61010-1 Hot Surface Warning"
LOGO2 LOGO4: library part CMP-0074835-1, "IEC 61010-1 High Voltage Warning"
Logo5: library part CMP-0074844-1
Logo6: library part CMP-0074838-1, "Texas Instrument Corporate Signature"
Logo7: library part CMP-0074847-1, "FCC_disclaimer"
Logo8: library part CMP-0074769-1
Q1 Q2: library part CMP-0078874-1, "600-V 12-A Single Channel GaN Power Stage, RWH0032A (VQFN-32)", Alternate Manufacturer="Texas Instruments", Alternate PartNumber=LMG3410R050RWHR
Q3: library part CMP-0000221-1, "MOSFET, N-CH, 20 V, 0.75 A, SOT-23", Alternate Manufacturer=None, Manufacturer="ON Semiconductor", Supplier Part Number 1=MGSF1N02LT1GOSCT-ND, Value1=0.1, Value2="6 nC"
R1: library part CMP-0025884-3, "RES, 0, 5%, 0.125 W, 0603", Manufacturer=Vishay/Beyschlag, Power_W=125mW, Supplier Part Number 1=MCT0603-0.0-ZZCT-ND, TempCo=ppm/C, Tolerance_%=5%, Value2=0.125W, Value_Code=0000, ValueDisplayed=0
R2: library part CMP-0025754-4, "RES, 20, 5%, 0.1 W, AEC-Q200 Grade 0, 0603", Manufacturer=Vishay-Dale, Power_W=100mW, Supplier Part Number 1=541-20GCT-ND, TempCo="200 ppm/C", Tolerance_%=5%, Value2=0.1W, Value_Code=20R0, ValueDisplayed=20
R3 R4 R8 R9: library part CMP-0026738-1, "RES, 49.9, 1%, 0.063 W, 0402", Manufacturer="Yageo America", Power_W=63mW, Supplier Part Number 1=311-49.9LRCT-ND, TempCo="100 ppm/C", Tolerance_%=1%, Value2=0.063W, Value_Code=49R9, ValueDisplayed=49.9
R5 R10: library part CMP-0026658-1, "RES, 10.0 k, 1%, 0.1 W, 0402", Manufacturer=Panasonic, Power_W=100mW, Supplier Part Number 1=P10.0KLCT-ND, TempCo="100 ppm/C", Tolerance_%=1%, Value2=0.1W, Value_Code=10k0, ValueDisplayed=10.0k
R6: library part CMP-0026842-3, "RES, 15 k, 5%, 0.063 W, AEC-Q200 Grade 0, 0402", Manufacturer=Vishay-Dale, Power_W=63mW, Supplier Part Number 1=541-15KJCT-ND, TempCo="200 ppm/C", Tolerance_%=5%, Value2=0.063W, Value_Code=15k0, ValueDisplayed=15k
R7: library part CMP-0015864-3, "RES, 0, 5%, 1 W, AEC-Q200 Grade 0, 2512", Manufacturer=Vishay-Dale, Power_W=1W, Supplier Part Number 1=541-0.0XCT-ND, TempCo=ppm/C, Tolerance_%=5%, Value_Code=0000, ValueDisplayed=0
R11: library part CMP-0026051-3, "RES, 17.8 k, 1%, 0.063 W, AEC-Q200 Grade 0, 0402", Manufacturer=Vishay-Dale, Power_W=63mW, Supplier Part Number 1=541-17.8KLCT-ND, TempCo="100 ppm/C", Tolerance_%=1%, Value2=0.063W, Value_Code=17k8, ValueDisplayed=17.8k
R12: library part CMP-0026745-1, "RES, 100 k, 1%, 0.063 W, 0402", Manufacturer="Samsung Electro-Mechanics", Power_W=63mW, Supplier Part Number 1=1276-3432-1-ND, TempCo="100 ppm/C", Tolerance_%=1%, Value2=0.063W, Value_Code=100k
T1 T2: library part CMP-0030718-1, "Transformer, 475uH, SMT", Manufacturer="Wurth Elektronik", Supplier Part Number 1=732-4458-1-ND, ValueDisplayed=475uH
TP1 TP2 TP3: library part CMP-0055044-1, "PCB Pin, 0.04\" DIA, Edge-Mount", Manufacturer=Mill-Max, Supplier Part Number 1=ED1278-ND
TP4: library part CMP-0055153-1, "Test Point, Compact, SMT", Manufacturer=Keystone, Supplier Part Number 1=36-5016TR-ND
U1 U3: library part CMP-0013035-2, "High Speed, Robust EMC Reinforced Triple-Channel Digital Isolator, DBQ0016A (SSOP-16)", Alternate Manufacturer="Texas Instruments", Alternate PartNumber=ISO7731DBQ
U2: library part CMP-0051578-2, "Single 2-Input Positive-AND Gate, DBV0005A (SOT-23-5)", Alternate Manufacturer="Texas Instruments", Alternate PartNumber=SN74AHC1G08DBVT, F @ Nom Voltage(Max)(Mhz)=75, Generic Part Number=SN74AHC1G08, ICC @ Nom Voltage(Max)(mA)=0.01, Operating Temperature Range(C)="-55 to 125", Rating=Catalog, tpd @ Nom Voltage(Max)(ns)=12.3,7.9, Voltage(Nom)(V)=3.3,5
U4 U5: library part CMP-0076095-1, "Low-Noise 1 A, 420 kHz Transformer Driver, DBV0006A (SOT-23-6)", Alternate Manufacturer="Texas Instruments", Alternate PartNumber=SN6505BDBVT
ZZ1: library part CMP-0077236-1
ZZ2: library part CMP-0077237-1
ZZ3: library part CMP-0077238-1
ZZ4: library part CMP-0077238-1, "These assemblies must comply with workmanship standards IPC-A-610 Class 2, unless otherwise specified."

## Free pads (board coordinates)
  round 140 hole 125: 2(127.68,1288.31) 2(1033.19,383.08)
  round 60 hole 30: 2(503,422) 2(932,528) 2(1067,1062) 2(1226.59,85) 2(1310.59,85)
  rect 74.8x44.88 smd far side: 3(1460.95,392.08) 3(1460.95,632.08) 3(1463.95,1129.08) 3(1465.59,887) 3(1785.95,642.08) 3(1786.23,522) 3(1786.95,402.08) 3(1788.95,1139.08) 3(1789.23,1019) 3(1789.45,899.08)

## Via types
v1: diameter 16, hole 8, Top Layer to Bottom Layer, 182 vias
v2: diameter 20, hole 12, Top Layer to Bottom Layer, tented both sides, 80 vias
v3: diameter 20, hole 10, Top Layer to Bottom Layer, tented both sides, 40 vias
v4: diameter 20, hole 12, Top Layer to Bottom Layer, tented top, 18 vias
v5: diameter 20, hole 12.1, Top Layer to Bottom Layer, tented both sides, 14 vias
v6: diameter 20, hole 12, Top Layer to Bottom Layer, 4 vias
v7: diameter 22, hole 10, Top Layer to Bottom Layer, tented both sides, 1 vias
v8: diameter 18, hole 8, Top Layer to Bottom Layer, tented both sides, 1 vias

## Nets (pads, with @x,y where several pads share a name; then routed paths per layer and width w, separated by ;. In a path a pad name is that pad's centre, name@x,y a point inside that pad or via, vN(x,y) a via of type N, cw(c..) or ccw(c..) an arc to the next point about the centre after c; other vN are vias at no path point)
5V: C1.1 C16.1 C29.1 C30.1 C31.1 C32.1 J1.3 pad.3@1786.23,522 pad.3@1789.23,1019 T1.5 T2.5 U1.1 U2.5 U3.1 U4.2 U4.5 U5.2 U5.5 | length 601.7
  Top Layer w10: U3.1@1747.28,372.5 1787.06,372.5 C16.1@1821.81,337.76 ; U1.1@1747.28,852.5 C1.1@1814.47,852.5
  Top Layer w12: C16.1@1822.58,336.99 v3(1853.6,336.99) ; C1.1@1825.59,841.38 v3(1854.97,841.38) 1884.94,841.38 U2.5@1889.19,837.13
  Bottom Layer w12: 1815.59,278.35 1815.59,350
  Bottom Layer w25: pad.3@1766.23,524 1770.88,519.35 U4.2@1855.46,519.35 ; U5.2@1860.46,1016 U5.5@1968.72,1016 ; 1885.59,519.35 U4.5@1963.72,519.35
  other v3: 1890.59,401 1856.59,689 1885.59,689 1894.91,1016 1895,1086.87 1851.49,1179.89 1877.49,1179.89
5V_H: C2.2 C5.1 Q1.25 R5.1 U1.16 | length 1628.9
  Top Layer w7: 902.24,804.66 902.24,871.17
  Top Layer w9: 701.74,876.8 703.86,876.8 711.11,884.05
  Top Layer w10: 832.24,817.17 851.19,798.22 851.19,796.17 ; 995,855 1095,855 1119.71,879.19 1214.7,879.19 1248.88,845 1319.51,845 1320.78,846.26 ; R5.1@1094.62,1112 1095.85,1110.78 1197.22,1110.78 1320.78,987.22 1320.78,846.26 ; U1.16@1532.72,852.5 1482.5,852.5 1460.38,830.38 C2.2@1427,830.38 1336.66,830.38 1320.78,846.26
  Top Layer w12: Q1.25@644.01,987.63 644.01,967.07 636.36,959.42 636.36,883.54 C5.1@664.73,855.17 686.36,876.8 701.74,876.8 ; 713.23,884.05 814.36,884.05 832.24,866.17 832.24,817.17 ; 851.19,796.17 893.75,796.17 902.24,804.66 ; 902.24,871.17 904.66,873.6 974.81,873.6 995,855
5V_L: C17.2 C20.1 Q2.25 R10.1 U3.16 | length 1702.3
  Top Layer w10: Q2.25@646.01,496.57 646.01,474.4 637.61,466 637.61,362.89 C20.1@658.5,342 691.5,375 717.89,375 727,384.11 ; 781.89,384.11 802.51,363.49 802.51,297.49 872,228 1244.04,228 1300,283.96 1300,323.38 ; R10.1@1094.62,612 1130,576.62 1130,474 1155,449 1155,324 ; 1155.38,323.38 1300,323.38 ; U3.16@1532.72,372.5 1479.71,372.5 C17.2@1430.59,323.38 1300,323.38
  Top Layer w12: 727,384.11 781.89,384.11
12V: J1.2 R7.1 | length 197.4
  Bottom Layer w50: 1568.86,231.14 R7.1@1656.14,230 ; J1.2@1570.59,111 1570.59,221.14
AGND: C1.2 C6.2 C16.2 C21.2 C29.2 C30.2 C31.2 C32.2 J1.1 U1.2 U1.4 U1.8 U2.3 U3.2 U3.8 U4.4 U4.6 U5.4 U5.6 | length 502.8
  Top Layer w10: U3.2@1747.28,397.5 1790.19,397.5 1803.46,384.23 C16.2@1822.58,384.23 ; U1.2@1747.28,877.5 C1.2@1814.47,877.5 ; U1.4@1747.28,927.5 1787.5,927.5 1810,950 v3(1810,980) ; U3.8@1750,550.22 v3(1750,580) ; U1.8@1752.6,1032.81 v2(1752.6,1060)
  Top Layer w12: C16.2@1822.58,384.23 v3(1854.82,384.23) ; C1.2@1825.59,888.62 1826.83,887.38 C6.2@1881.59,887.38 ; C21.2@1874.83,485 1913.09,485 1916.09,482 v3(1933.59,482) ; v3(1963.59,682) 1963.99,682.4 U2.3@1963.99,728.87
  other v3: 1944.59,458.5 1970.59,584 1853.59,886 1979.48,948.9 2005,975 2005,1080 1942.85,1084.1
  other v7: 1942.59,584
BOT_FET: J1.5 R8.1 | length 496.2
  Top Layer w12: J1.5@1870.59,111 1935.5,175.91 1935.5,308.91 1971.59,345 1971.59,521 1951.59,541 R8.1@1935.5,541
FAULT_H: C7.1 Q1.32 U1.12 | length 949.6
  Top Layer w10: 1313.24,1176.17 1358.38,1131.03 C7.1@1358.38,1087 1492.88,952.5 U1.12@1532.72,952.5
  Top Layer w12: Q1.32@716.84,1139.2 753.81,1176.17 1313.24,1176.17
FAULT_L: C22.1 Q2.32 U3.12 | length 959.1
  Top Layer w10: Q2.32@718.84,644.2 718.84,674.84 735.24,691.24 915.87,691.24 936.61,670.5 1145.5,670.5 1166.24,691.24 1173.76,691.24 1264,601 1369,601 1497.5,472.5 U3.12@1532.72,472.5
GAN_FAULT: J1.4 U2.4 | length 866.7
  Top Layer w12: v3(1963.59,789) 1963.99,789.4 U2.4@1963.99,837.13
  Bottom Layer w12: J1.4@1770.59,111 2036.59,377 2036.59,684 1963.59,757 v3(1963.59,789)
HVBUS: C9.1 C10.1 C11.1 C12.1 C13.1 C14.1 Q1.1 Q1.2 Q1.3 Q1.4 Q1.5 Q1.6 Q1.7 Q1.8 Q1.9 Q1.10 Q1.11 TP2.1
  other v2: 944,1281 970,1281 997,1281 1022,1281 817,1282 843,1282 869,1282 894,1282 920,1282 944,1306 970,1306 997,1306 1022,1306 817,1307 843,1307 869,1307 894,1307 920,1307
  other v4: 135,1040 165,1060 135,1070 165,1085 135,1100 195,1100 165,1110 135,1130 195,1130 225,1130 165,1145 195,1160 225,1160 235,1190 250,1210 275,1215 280,1240 280,1270
IN_H: C3.2 Q1.31 R4.2
IN_L: C19.2 Q2.31 R9.2
ISO_12V_H: C28.1 D5.1 L4.1 R1.1 | length 70.3
  Bottom Layer w25: v3(1270.32,926) 1270.32,897.55 L4.1@1270.32,939.41
  other v3: 1270.2,898.45
ISO_12V_H_B: C26.1 D3.1 L4.4 | length 308
  Bottom Layer w25: 1373.59,1030.3 1373.59,1061.53 1373.59,1030.3 ; 1373.59,1030.3 1396.99,1006.9 1396.99,970.44 1396.59,970.04 1396.59,967 1369,939.41 L4.4@1360.87,939.41 1375.59,924.69 ; 1375.59,924.69 1375.59,872.5 1375.59,924.69
ISO_12V_L: C18.1 C27.1 D1.2 D4.1 L3.1 pad.2@1310.59,85 Q2.27 R7.2 | length 2057.7
  Top Layer w10: C18.1@758,436.93 758,406 763,401 793.93,401 820.39,374.54 820.39,319.61 ; 838.5,303.5 C27.1@861,303.5 913.94,303.5 961.44,256 ; D4.1@1164.47,526 1217,526 1239,504 v3@1239,492 ; v3@1215.28,769 v3(1217,769)
  Top Layer w20: 825,315 924.49,315 981.41,258.08 1084.97,258.08 1116.3,289.41 v3(1254.59,289.41)
  Top Layer w25: D1.2@1159.15,790.17 1194.11,790.17 v3@1215.28,769 ; Q2.27@704.06,497.57 754,450 705.09,496.59 Q2.27@704.06,497.57
  MidLayer2 w25: v3(1217,769) 1239.69,746.31 1239.69,721.17 1239.75,492 1239.78,393.17 1239.78,304.22 v3(1254.59,289.41) 1328,216 v3(1364.55,216)
  Bottom Layer w25: v3(1254.59,289.41) 1240.88,303.12 1240.88,377.97 L3.1@1264.32,401.41 ; pad.2@1310.59,85 R7.2@1423.86,198.27 ; v3(1364.55,216) R7.2@1429,216
  other v3: 1239,483
ISO_12V_L_B: C25.1 D2.1 L3.4 | length 203.9
  Bottom Layer w25: C25.1@1357.59,355.5 1354.87,358.22 L3.4@1354.87,401.41 1382,401.41 1398.59,418 1398.59,487.53 D2.1@1372.59,513.53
